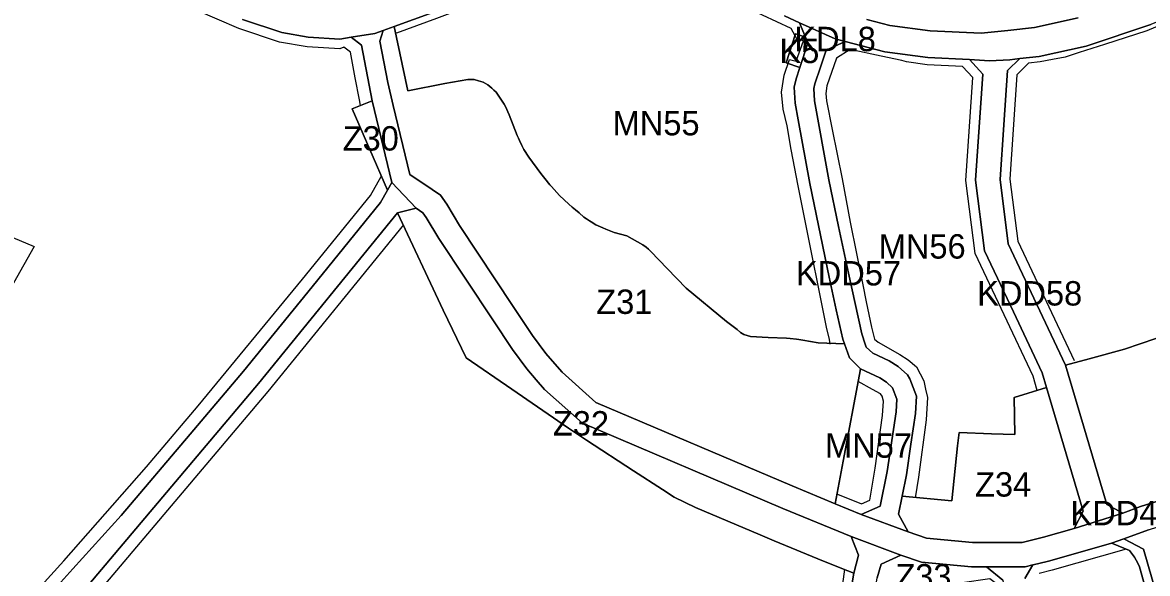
# Model space of a CAD drawing. Extents: x 7428841 to 7433518, y 5545054 to 5546840.
# Drawn here: x 7432461.8 to 7432923.5, y 5545858.6 to 5546084.6 of the extents above; entities that cross this region are included whole.
import ezdxf

# ---------------------------------------------------------------- set-up
doc = ezdxf.new("R2010")
doc.units = 0
for name, color, linetype in [('linie_rozgraniczajace', 7, 'Continuous'), ('linie_zabudowy_nieprzekraczalne', 7, 'Continuous'), ('oznaczenia_przeznaczen', 7, 'Continuous')]:
    doc.layers.add(name, color=color, linetype=linetype)

msp = doc.modelspace()

# ---------------------------------------------------------------- linework, layer by layer
at = {"layer": 'linie_rozgraniczajace'}
for points in [[(7432942.31, 5546090.87), (7432924.89, 5546083.84), (7432898.36, 5546074.96), (7432879.11, 5546070.63), (7432871.18, 5546069.83), (7432867.06, 5546069.26), (7432858.66, 5546068.83), (7432850.43, 5546069.48), (7432833.4, 5546070.19), (7432815.67, 5546072.58), (7432799.51, 5546076.76), (7432795.3, 5546077.85), (7432780.74, 5546084.48), (7432774.59, 5546087.28)], [(7432630.2, 5546088.67), (7432614.31, 5546083.01), (7432609.86, 5546081.37), (7432606.39, 5546080.09), (7432596.63, 5546078.55), (7432591.97, 5546077.81), (7432579.07, 5546078.61), (7432568.2, 5546080.47), (7432552.06, 5546085.88)], [(7432774.59, 5546087.28), (7432780.74, 5546084.48), (7432783.16, 5546078.58), (7432782.39, 5546078.83), (7432779.07, 5546079.91), (7432775.22, 5546068.01), (7432780.83, 5546066.2), (7432779.27, 5546061.54), (7432778.54, 5546058.15), (7432778.89, 5546051.54), (7432780.11, 5546044.67), (7432784.92, 5546018.58), (7432792.93, 5545980.13), (7432795.73, 5545966.79), (7432797.12, 5545960.77), (7432798.51, 5545954.76), (7432799.14, 5545952.86), (7432788.37, 5545953.18), (7432782.07, 5545954.34), (7432780.44, 5545954.64), (7432779.47, 5545954.73), (7432776.86, 5545955.04), (7432775.3, 5545955.12), (7432767.9, 5545955.42), (7432760.63, 5545955.8), (7432757.79, 5545956.71), (7432756.52, 5545957.53), (7432755.16, 5545958.76), (7432752.95, 5545960.39), (7432750.73, 5545962.02), (7432734.17, 5545975.71), (7432726.34, 5545983.74), (7432719.63, 5545990.67), (7432718.73, 5545991.59), (7432717.77, 5545992.42), (7432716.43, 5545993.36), (7432709.81, 5545997.08), (7432707.2, 5545997.8), (7432704.6, 5545998.52), (7432701.17, 5545999.8), (7432699.92, 5546000.4), (7432697.13, 5546001.68), (7432696.47, 5546002.04), (7432695.82, 5546002.4), (7432694.52, 5546003.22), (7432693.31, 5546004.05), (7432692.2, 5546004.82), (7432690.23, 5546006.6), (7432688.8, 5546007.74), (7432687.36, 5546008.88), (7432685.97, 5546010.07), (7432684.1, 5546011.89), (7432682.22, 5546013.62), (7432679.94, 5546016.12), (7432678.85, 5546017.32), (7432678.27, 5546018.01), (7432676.19, 5546020.64), (7432674.52, 5546022.65), (7432669.56, 5546029.41), (7432667.61, 5546032.52), (7432666.78, 5546034.23), (7432665.79, 5546036.25), (7432665.38, 5546037.2), (7432664.81, 5546038.27), (7432663.18, 5546042.51), (7432661.54, 5546046.75), (7432659.99, 5546050.18), (7432659.42, 5546051.1), (7432657.49, 5546054.02), (7432656.14, 5546056.02), (7432655.29, 5546056.87), (7432654.43, 5546057.72), (7432652.76, 5546059.02), (7432650.81, 5546060.11), (7432648.97, 5546060.74), (7432647.22, 5546061.17), (7432644.52, 5546061.27), (7432635.1, 5546059.59), (7432619.9, 5546056.53), (7432614.31, 5546083.01), (7432630.2, 5546088.67)], [(7432895.13, 5546086.53), (7432877.19, 5546082.5), (7432866.19, 5546081.39), (7432855.2, 5546080.29), (7432834.37, 5546081.16), (7432817.79, 5546083.39), (7432808.39, 5546085.83)], [(7432877.19, 5546082.5), (7432895.13, 5546086.53)], [(7432552.06, 5546085.88), (7432568.2, 5546080.47), (7432579.07, 5546078.61), (7432591.97, 5546077.81), (7432596.63, 5546078.55), (7432600.91, 5546075.33), (7432605.26, 5546052.46), (7432597.08, 5546049.19), (7432611.56, 5546015.86), (7432608.76, 5546010.8), (7432580.61, 5545976.21), (7432552.47, 5545941.62), (7432530.57, 5545915.74), (7432502.33, 5545882.37), (7432482.47, 5545860.49), (7432462.66, 5545838.66)], [(7432808.39, 5546085.83), (7432817.79, 5546083.39), (7432834.37, 5546081.16), (7432855.2, 5546080.29), (7432866.19, 5546081.39), (7432877.19, 5546082.5)], [(7432933.34, 5545957.17), (7432914.09, 5545950.7), (7432899.55, 5545946.71), (7432889.83, 5545944.04), (7432866.4, 5545993.79), (7432863.04, 5546020.27), (7432864.54, 5546042.59), (7432866.04, 5546064.92), (7432871.18, 5546069.83), (7432879.11, 5546070.63), (7432898.36, 5546074.96), (7432924.89, 5546083.84)], [(7432596.63, 5546078.55), (7432606.39, 5546080.09), (7432609.86, 5546081.37), (7432608.39, 5546076.93), (7432611.68, 5546059.99), (7432613.94, 5546050.57), (7432620.74, 5546022.3), (7432629.9, 5546016.09), (7432633.3, 5546013.78), (7432635.88, 5546010.06), (7432641.16, 5546001.32), (7432663.11, 5545968.16), (7432671.07, 5545956.21), (7432676.61, 5545948.85), (7432680.22, 5545944.62), (7432683.22, 5545941.18), (7432697.09, 5545928.78), (7432777.71, 5545894.54), (7432795.37, 5545887.26), (7432806.02, 5545882.86), (7432825.26, 5545875.66), (7432832.87, 5545873.1), (7432851.72, 5545871.31), (7432872.06, 5545871.39), (7432880.86, 5545873.49), (7432893.38, 5545877.07), (7432913.41, 5545883.41), (7432920.69, 5545886.06), (7432937.92, 5545891.47)], [(7432626.14, 5546006.55), (7432623.4, 5546008.41), (7432613.3, 5546018.99), (7432605.26, 5546052.46), (7432600.91, 5546075.33), (7432596.63, 5546078.55)], [(7432462.66, 5545838.66), (7432482.47, 5545860.49), (7432502.33, 5545882.37), (7432530.57, 5545915.74), (7432552.47, 5545941.62), (7432580.61, 5545976.21), (7432608.76, 5546010.8), (7432611.56, 5546015.86), (7432613.3, 5546018.99), (7432623.4, 5546008.41), (7432615.64, 5546006.52), (7432558.63, 5545936.52), (7432481.55, 5545845.41)], [(7432481.55, 5545845.41), (7432558.63, 5545936.52), (7432615.64, 5546006.52), (7432634.43, 5545966.67), (7432643.87, 5545947.04), (7432662.6, 5545934.17), (7432685.87, 5545918.22), (7432693.24, 5545913.37), (7432712.53, 5545900.77), (7432724.44, 5545893.01), (7432729.29, 5545889.98), (7432737.98, 5545885.68), (7432764.49, 5545874.48), (7432770.28, 5545872.05), (7432790.56, 5545863.63), (7432800.59, 5545859.73), (7432802.96, 5545858.8), (7432800.11, 5545842.14)], [(7432923.9, 5545876.59), (7432913.81, 5545872.91), (7432908.71, 5545871.05), (7432883.4, 5545863.82), (7432878.33, 5545862.6), (7432876.5, 5545862.17), (7432873.26, 5545861.39), (7432857.39, 5545861.33), (7432851.27, 5545861.31), (7432830.78, 5545863.26), (7432822.35, 5545866.09), (7432801.9, 5545873.84), (7432773.86, 5545885.31), (7432691.66, 5545920.22), (7432676.08, 5545934.14), (7432672.65, 5545938.09), (7432668.8, 5545942.58), (7432662.9, 5545950.43), (7432654.78, 5545962.63), (7432632.71, 5545995.97), (7432627.48, 5546004.62), (7432626.14, 5546006.55)], [(7432937.92, 5545891.47), (7432920.69, 5545886.06), (7432913.41, 5545883.41), (7432906.82, 5545886.96), (7432889.83, 5545944.04), (7432899.55, 5545946.71), (7432914.09, 5545950.7), (7432933.34, 5545957.17)], [(7432800.11, 5545842.14), (7432802.96, 5545858.8), (7432804.85, 5545866.12), (7432801.9, 5545873.84), (7432822.35, 5545866.09), (7432814.2, 5545862.45), (7432812.61, 5545856.87)], [(7432873.21, 5545856.56), (7432876.5, 5545862.17), (7432878.33, 5545862.6), (7432883.4, 5545863.82), (7432908.71, 5545871.05), (7432909.17, 5545870.87), (7432916.14, 5545868.05), (7432918.17, 5545865.36), (7432919.55, 5545862.9), (7432920.2, 5545861.37), (7432924.46, 5545846.25)], [(7432924.46, 5545846.25), (7432920.2, 5545861.37), (7432919.55, 5545862.9), (7432918.17, 5545865.36), (7432916.14, 5545868.05), (7432909.17, 5545870.87), (7432908.71, 5545871.05), (7432913.81, 5545872.91), (7432921.87, 5545868.65), (7432956.87, 5545747.44)], [(7432864.1, 5545855.86), (7432857.39, 5545861.33), (7432873.26, 5545861.39), (7432876.5, 5545862.17), (7432873.21, 5545856.56)]]:
    msp.add_lwpolyline(points, dxfattribs=at)
for points in [[(7432608.39, 5546076.93), (7432609.86, 5546081.37), (7432614.31, 5546083.01), (7432619.9, 5546056.53), (7432635.1, 5546059.59), (7432644.52, 5546061.27), (7432647.22, 5546061.17), (7432648.97, 5546060.74), (7432650.81, 5546060.11), (7432652.76, 5546059.02), (7432654.43, 5546057.72), (7432655.29, 5546056.87), (7432656.14, 5546056.02), (7432657.49, 5546054.02), (7432659.42, 5546051.1), (7432659.99, 5546050.18), (7432661.54, 5546046.75), (7432663.18, 5546042.51), (7432664.81, 5546038.27), (7432665.38, 5546037.2), (7432665.79, 5546036.25), (7432666.78, 5546034.23), (7432667.61, 5546032.52), (7432669.56, 5546029.41), (7432674.52, 5546022.65), (7432676.19, 5546020.64), (7432678.27, 5546018.01), (7432678.85, 5546017.32), (7432679.94, 5546016.12), (7432682.22, 5546013.62), (7432684.1, 5546011.89), (7432685.97, 5546010.07), (7432687.36, 5546008.88), (7432688.8, 5546007.74), (7432690.23, 5546006.6), (7432692.2, 5546004.82), (7432693.31, 5546004.05), (7432694.52, 5546003.22), (7432695.82, 5546002.4), (7432696.47, 5546002.04), (7432697.13, 5546001.68), (7432699.92, 5546000.4), (7432701.17, 5545999.8), (7432704.6, 5545998.52), (7432707.2, 5545997.8), (7432709.81, 5545997.08), (7432716.43, 5545993.36), (7432717.77, 5545992.42), (7432718.73, 5545991.59), (7432719.63, 5545990.67), (7432726.34, 5545983.74), (7432734.17, 5545975.71), (7432750.73, 5545962.02), (7432752.95, 5545960.39), (7432755.16, 5545958.76), (7432756.52, 5545957.53), (7432757.79, 5545956.71), (7432760.63, 5545955.8), (7432767.9, 5545955.42), (7432775.3, 5545955.12), (7432776.86, 5545955.04), (7432779.47, 5545954.73), (7432780.44, 5545954.64), (7432782.07, 5545954.34), (7432788.37, 5545953.18), (7432799.14, 5545952.86), (7432801.21, 5545947.03), (7432805.8, 5545942.62), (7432805.35, 5545940.26), (7432798.62, 5545904.76), (7432795.37, 5545887.26), (7432777.71, 5545894.54), (7432697.09, 5545928.78), (7432683.22, 5545941.18), (7432680.22, 5545944.62), (7432676.61, 5545948.85), (7432671.07, 5545956.21), (7432663.11, 5545968.16), (7432641.16, 5546001.32), (7432635.88, 5546010.06), (7432633.3, 5546013.78), (7432629.9, 5546016.09), (7432620.74, 5546022.3), (7432613.94, 5546050.57), (7432611.68, 5546059.99)], [(7432778.54, 5546058.15), (7432779.27, 5546061.54), (7432780.83, 5546066.2), (7432784.16, 5546076.14), (7432783.16, 5546078.58), (7432780.74, 5546084.48), (7432795.3, 5546077.85), (7432799.51, 5546076.76), (7432791.63, 5546073.25), (7432789.31, 5546066.33), (7432787, 5546059.42), (7432786.59, 5546057.51), (7432786.86, 5546052.46), (7432792.77, 5546020.12), (7432796.77, 5546000.94), (7432800.76, 5545981.76), (7432806.22, 5545956.93), (7432807.67, 5545952.67), (7432808.09, 5545951.51), (7432810.75, 5545948.96), (7432817.48, 5545945.9), (7432821.24, 5545943.52), (7432825.01, 5545940.04), (7432826.05, 5545938.49), (7432828.7, 5545931.36), (7432828.29, 5545924.19), (7432826.45, 5545911.61), (7432824.61, 5545899.03), (7432822.82, 5545890.41), (7432821.27, 5545882.99), (7432825.26, 5545875.66), (7432806.02, 5545882.86), (7432813.82, 5545886.18), (7432816.73, 5545900.41), (7432820.32, 5545925), (7432820.62, 5545930.14), (7432818.89, 5545934.81), (7432816.36, 5545937.14), (7432813.66, 5545938.84), (7432805.8, 5545942.62), (7432801.21, 5545947.03), (7432799.14, 5545952.86), (7432798.51, 5545954.76), (7432797.12, 5545960.77), (7432795.73, 5545966.79), (7432792.93, 5545980.13), (7432784.92, 5546018.58), (7432780.11, 5546044.67), (7432778.89, 5546051.54)], [(7432775.22, 5546068.01), (7432779.07, 5546079.91), (7432782.39, 5546078.83), (7432783.16, 5546078.58), (7432784.16, 5546076.14), (7432780.83, 5546066.2)], [(7432786.59, 5546057.51), (7432787, 5546059.42), (7432789.31, 5546066.33), (7432791.63, 5546073.25), (7432799.51, 5546076.76), (7432815.67, 5546072.58), (7432833.4, 5546070.19), (7432850.43, 5546069.48), (7432855.92, 5546063.41), (7432854.46, 5546041.69), (7432853, 5546019.97), (7432856.68, 5545990.96), (7432868.5, 5545965.94), (7432880.33, 5545940.93), (7432882.12, 5545934.92), (7432868.77, 5545930.85), (7432869.1, 5545915.62), (7432859.54, 5545915.95), (7432846.17, 5545916.41), (7432845.61, 5545911.03), (7432843.27, 5545888.42), (7432822.82, 5545890.41), (7432824.61, 5545899.03), (7432826.45, 5545911.61), (7432828.29, 5545924.19), (7432828.7, 5545931.36), (7432826.05, 5545938.49), (7432825.01, 5545940.04), (7432821.24, 5545943.52), (7432817.48, 5545945.9), (7432810.75, 5545948.96), (7432808.09, 5545951.51), (7432807.67, 5545952.67), (7432806.22, 5545956.93), (7432800.76, 5545981.76), (7432796.77, 5546000.94), (7432792.77, 5546020.12), (7432786.86, 5546052.46)], [(7432850.43, 5546069.48), (7432858.66, 5546068.83), (7432867.06, 5546069.26), (7432871.18, 5546069.83), (7432866.04, 5546064.92), (7432864.54, 5546042.59), (7432863.04, 5546020.27), (7432866.4, 5545993.79), (7432889.83, 5545944.04), (7432906.82, 5545886.96), (7432913.41, 5545883.41), (7432893.38, 5545877.07), (7432897.19, 5545884.26), (7432882.12, 5545934.92), (7432880.33, 5545940.93), (7432868.5, 5545965.94), (7432856.68, 5545990.96), (7432853, 5546019.97), (7432854.46, 5546041.69), (7432855.92, 5546063.41)], [(7432597.08, 5546049.19), (7432605.26, 5546052.46), (7432613.3, 5546018.99), (7432611.56, 5546015.86)], [(7432615.64, 5546006.52), (7432623.4, 5546008.41), (7432626.14, 5546006.55), (7432627.48, 5546004.62), (7432632.71, 5545995.97), (7432654.78, 5545962.63), (7432662.9, 5545950.43), (7432668.8, 5545942.58), (7432672.65, 5545938.09), (7432676.08, 5545934.14), (7432691.66, 5545920.22), (7432773.86, 5545885.31), (7432801.9, 5545873.84), (7432804.85, 5545866.12), (7432802.96, 5545858.8), (7432800.59, 5545859.73), (7432790.56, 5545863.63), (7432770.28, 5545872.05), (7432764.49, 5545874.48), (7432737.98, 5545885.68), (7432729.29, 5545889.98), (7432724.44, 5545893.01), (7432712.53, 5545900.77), (7432693.24, 5545913.37), (7432685.87, 5545918.22), (7432662.6, 5545934.17), (7432643.87, 5545947.04), (7432634.43, 5545966.67)], [(7432795.37, 5545887.26), (7432798.62, 5545904.76), (7432805.35, 5545940.26), (7432805.8, 5545942.62), (7432813.66, 5545938.84), (7432816.36, 5545937.14), (7432818.89, 5545934.81), (7432820.62, 5545930.14), (7432820.32, 5545925), (7432816.73, 5545900.41), (7432813.82, 5545886.18), (7432806.02, 5545882.86)], [(7432821.27, 5545882.99), (7432822.82, 5545890.41), (7432843.27, 5545888.42), (7432845.61, 5545911.03), (7432846.17, 5545916.41), (7432859.54, 5545915.95), (7432869.1, 5545915.62), (7432868.77, 5545930.85), (7432882.12, 5545934.92), (7432897.19, 5545884.26), (7432893.38, 5545877.07), (7432880.86, 5545873.49), (7432872.06, 5545871.39), (7432851.72, 5545871.31), (7432832.87, 5545873.1), (7432825.26, 5545875.66)], [(7432913.81, 5545872.91), (7432923.9, 5545876.59), (7432936.22, 5545880.45), (7432931.59, 5545870.85), (7432949.02, 5545810.6), (7432966.44, 5545750.35), (7432973, 5545729.74), (7432982.59, 5545713.04), (7432986.98, 5545710.36), (7433009.42, 5545658.54), (7433019.91, 5545633.44), (7433029.91, 5545629.41), (7433039.48, 5545632.62), (7433025.51, 5545613.51), (7433022.56, 5545619.44), (7433014.46, 5545620.66), (7433012.2, 5545621.38), (7433000.13, 5545654.83), (7432979.02, 5545703.38), (7432975.91, 5545705.16), (7432963.81, 5545725.63), (7432956.87, 5545747.44), (7432921.87, 5545868.65)], [(7432810.88, 5545846.1), (7432812.61, 5545856.87), (7432814.2, 5545862.45), (7432822.35, 5545866.09), (7432830.78, 5545863.26), (7432851.27, 5545861.31), (7432857.39, 5545861.33), (7432864.1, 5545855.86), (7432864.64, 5545852.13), (7432858.88, 5545856.47), (7432836.13, 5545853.1), (7432819.32, 5545850.62)]]:
    msp.add_lwpolyline(points, close=True, dxfattribs=at)
at = {"layer": 'linie_zabudowy_nieprzekraczalne'}
for points in [[(7432593.63, 5546074.54), (7432591.98, 5546073.8), (7432578.61, 5546074.63), (7432567.22, 5546076.58), (7432550.63, 5546082.14), (7432532.81, 5546089.84), (7432527.7, 5546092.2), (7432485.7, 5546109.81), (7432458.51, 5546126.69), (7432452.41, 5546132.85), (7432435.28, 5546145.13), (7432424.99, 5546147.09), (7432418.39, 5546143.95), (7432409.65, 5546135.03), (7432399.48, 5546106.93), (7432393.88, 5546092.12), (7432381.68, 5546060.94), (7432377.92, 5546051.34), (7432372.72, 5546035.31)], [(7432777.26, 5546082.2), (7432753.74, 5546093.14), (7432752.37, 5546094.1), (7432744.22, 5546099.25), (7432740.25, 5546101.96), (7432730.64, 5546108.86), (7432729.04, 5546109.98), (7432725.38, 5546110.39), (7432719.04, 5546109.31), (7432713.98, 5546108.14), (7432708.85, 5546106.93), (7432705.05, 5546106.58), (7432698.44, 5546105.8), (7432684.95, 5546104.67), (7432674.89, 5546103.49), (7432670.65, 5546102.46), (7432664.16, 5546099.31), (7432654.76, 5546095.45), (7432648.15, 5546092.41), (7432631.69, 5546086.29), (7432615.32, 5546080.29)], [(7432940.13, 5546088.26), (7432923.27, 5546081.18), (7432905.94, 5546075.63), (7432895.54, 5546072.28), (7432889.7, 5546070.44), (7432884.6, 5546069.46), (7432879.5, 5546068.48), (7432874.69, 5546067.96)], [(7432793.25, 5545952.68), (7432793.03, 5545954.56), (7432791.78, 5545959.68), (7432790.54, 5545965.75), (7432783.89, 5545999.13), (7432780.17, 5546017.6), (7432777.23, 5546032.5), (7432775.64, 5546042.24), (7432773.98, 5546049), (7432773.33, 5546056.09), (7432774.39, 5546062.96), (7432776.58, 5546069.49), (7432779.39, 5546068.7), (7432782.35, 5546077.11), (7432779.66, 5546077.9), (7432777.26, 5546082.2)], [(7432600.57, 5546050.61), (7432600.1, 5546052.86), (7432598.37, 5546061.95), (7432596.36, 5546072.5), (7432593.63, 5546074.54)], [(7432801.49, 5546073.5), (7432795.92, 5546070.05), (7432791.93, 5546058.58), (7432791.46, 5546055.54), (7432791.74, 5546052.53), (7432794.12, 5546040.71), (7432798.16, 5546020.56), (7432801.53, 5546002.69), (7432806.69, 5545977.08), (7432808.04, 5545970.04), (7432810.25, 5545959.7), (7432811.48, 5545954.69), (7432813.05, 5545953.46), (7432821.91, 5545948.44), (7432825.28, 5545946.29), (7432828.68, 5545943.38), (7432831.71, 5545937.64), (7432832.48, 5545934.23), (7432833.26, 5545930.83), (7432832.71, 5545921.66), (7432829.54, 5545898.14), (7432828.24, 5545889.69)], [(7432847.66, 5546066.59), (7432833.14, 5546067.2), (7432824.56, 5546068.48), (7432822.67, 5546068.96), (7432814.2, 5546070.8), (7432801.49, 5546073.5)], [(7432874.69, 5546067.96), (7432869.93, 5546063.1), (7432867.06, 5546020.39), (7432870.29, 5545994.93), (7432893.44, 5545945.95)], [(7432878.3, 5545933.71), (7432876.58, 5545939.5), (7432852.79, 5545989.82), (7432848.99, 5546019.85), (7432851.81, 5546061.99), (7432847.63, 5546066.62)], [(7432372.69, 5546035.2), (7432376.74, 5546026.61), (7432438.68, 5545999.12), (7432444.72, 5546001.89), (7432466.59, 5545992.69), (7432452.49, 5545968.04), (7432432.77, 5545976.56), (7432431.48, 5545982.83), (7432370.24, 5546010.05), (7432363.46, 5546007.84)], [(7432553.71, 5545656.87), (7432535.29, 5545673.24), (7432519.45, 5545687.14), (7432507.2, 5545698.97), (7432503.13, 5545703.79), (7432500.72, 5545708.71), (7432499.42, 5545713.29), (7432491.95, 5545778.42), (7432488.57, 5545817.36), (7432487.85, 5545818.9), (7432476.64, 5545826.01), (7432470.39, 5545828.94), (7432465.86, 5545831.11), (7432463.4, 5545832.33), (7432454.78, 5545837.43), (7432478.74, 5545863.82), (7432512.66, 5545902.33), (7432533.86, 5545927.37), (7432576.75, 5545979.38), (7432604.6, 5546013.61), (7432608.93, 5546021.42)], [(7432618.1, 5546001.67), (7432562.48, 5545933.32), (7432525.76, 5545889.94), (7432498.81, 5545858.08), (7432486.83, 5545843.91), (7432487.35, 5545840.44), (7432501.92, 5545831.32), (7432506.28, 5545821.97), (7432509.87, 5545780.1), (7432517.13, 5545716.81), (7432518.21, 5545713.86), (7432520.26, 5545711.39), (7432541.01, 5545692.16), (7432552.5, 5545682.35)], [(7432806.12, 5545887.15), (7432809.56, 5545888.64), (7432811.73, 5545901.77), (7432814.78, 5545923.45), (7432815.14, 5545929.34), (7432814.69, 5545931.33), (7432813.97, 5545932.27), (7432810.66, 5545934.03), (7432804.78, 5545937.41)], [(7432795.95, 5545891.33), (7432796.92, 5545890.92), (7432806.12, 5545887.15)], [(7432914.76, 5545868.62), (7432884.42, 5545859.95), (7432879.08, 5545858.67)], [(7432695.36, 5545561.62), (7432700.58, 5545587.88), (7432704.91, 5545605.53), (7432707.27, 5545612.64), (7432721.28, 5545651), (7432735.53, 5545683.2), (7432746.17, 5545705.98), (7432757.15, 5545728.45), (7432775.79, 5545760.35), (7432791.15, 5545790.68), (7432794.62, 5545804.39), (7432795.08, 5545814.24), (7432795.4, 5545826.14), (7432797.74, 5545849.15), (7432799.24, 5545860.38)]]:
    msp.add_lwpolyline(points, dxfattribs=at)

# ---------------------------------------------------------------- texts
at = {"layer": 'oznaczenia_przeznaczen'}
for s, p in [('KDL8', (7432778.58, 5546072.85)), ('K5', (7432772.48, 5546067.96)), ('MN55', (7432704.01, 5546038.33)), ('Z30', (7432593.19, 5546032.09)), ('MN56', (7432813.23, 5545987.78)), ('KDD57', (7432779.27, 5545976.76)), ('KDD58', (7432853.62, 5545968.53)), ('Z31', (7432697.28, 5545965.1)), ('Z32', (7432679.48, 5545915.22)), ('MN57', (7432791.2, 5545906.12)), ('Z34', (7432852.75, 5545890.18)), ('KDD47', (7432891.92, 5545878.41)), ('Z33', (7432820.06, 5545852.49))]:
    msp.add_text(s, height=10, dxfattribs=at).set_placement(p)

doc.saveas('drawing.dxf')
